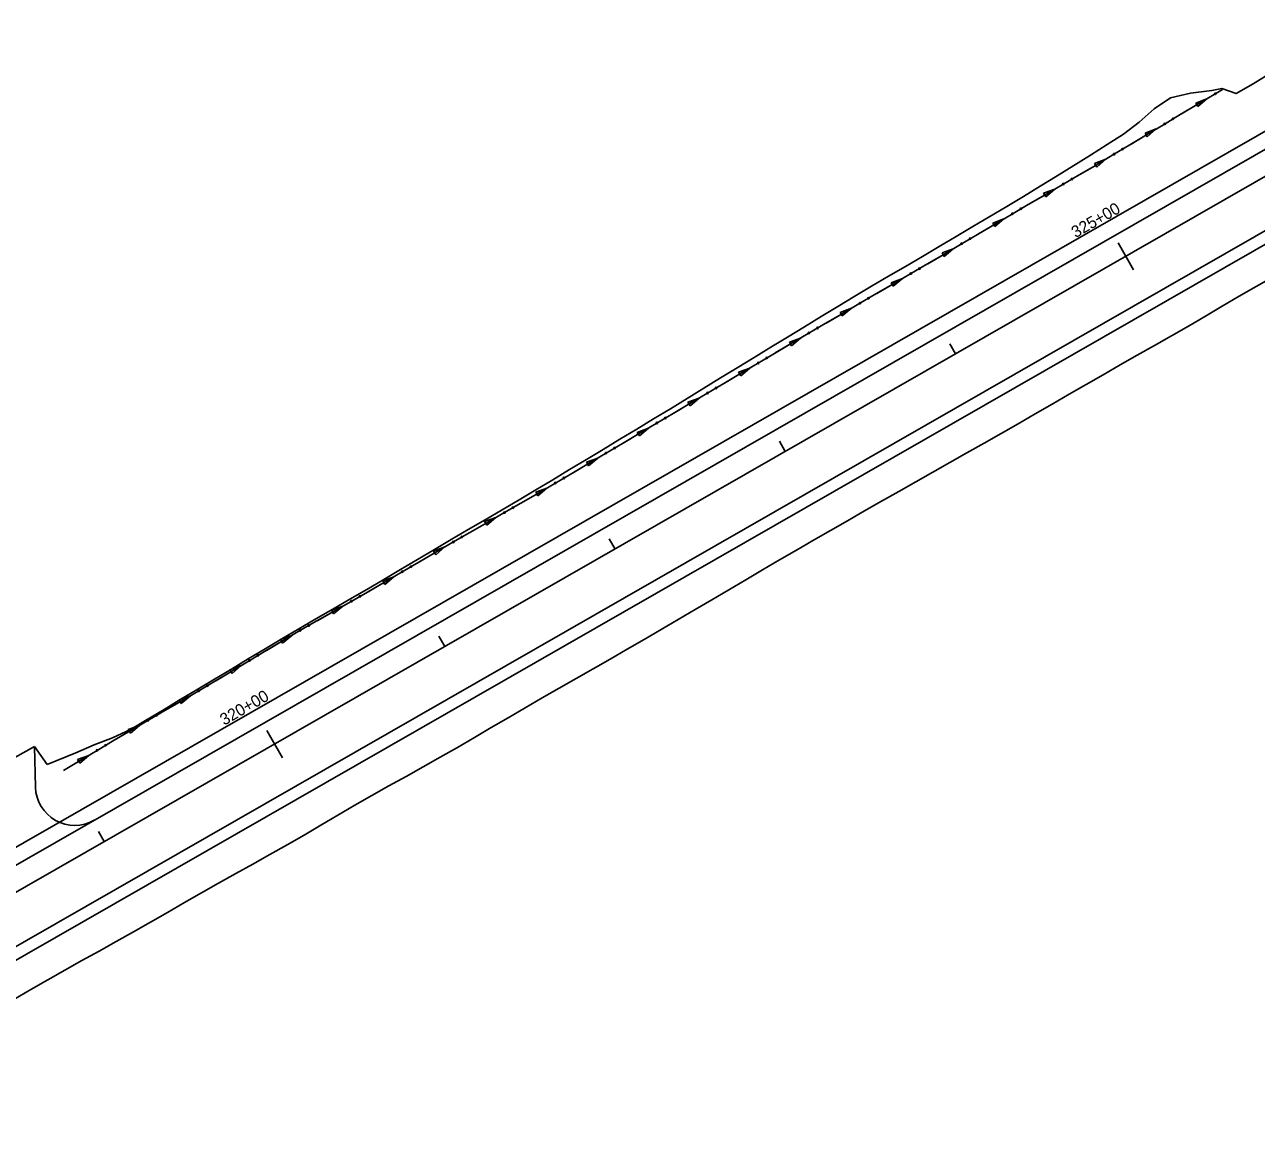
# Model space of a CAD drawing. Extents: x 1375694 to 1433473, y 1931050 to 1967991.
# Drawn here: x 1418280 to 1418908, y 1956117 to 1956684 of the extents above; entities that cross this region are included whole.
import ezdxf

# ---------------------------------------------------------------- set-up
doc = ezdxf.new("R2010")
doc.units = 0
for name, color, linetype in [('62', 7, 'Continuous'), ('R_Horz Alg', 7, 'Continuous'), ('R_Horz Alg Annot', 7, 'Continuous'), ('R_Proposed Const Limits', 7, 'Continuous'), ('R_Proposed Road', 7, 'Continuous')]:
    doc.layers.add(name, color=color, linetype=linetype)

msp = doc.modelspace()

# ---------------------------------------------------------------- linework, layer by layer
at = {"layer": '62'}
for p, q in [((1418882.71, 1956645.8), (1418877.01, 1956643.66)), ((1418877.01, 1956643.66), (1418878.08, 1956641.84)), ((1418878.08, 1956641.84), (1418882.71, 1956645.8)), ((1418856.9, 1956630.44), (1418851.21, 1956628.26)), ((1418852.29, 1956626.45), (1418856.9, 1956630.44)), ((1418851.21, 1956628.26), (1418852.29, 1956626.45)), ((1418831.13, 1956615), (1418825.44, 1956612.82)), ((1418825.44, 1956612.82), (1418826.53, 1956611.01)), ((1418826.53, 1956611.01), (1418831.13, 1956615)), ((1418805.22, 1956599.81), (1418799.5, 1956597.7)), ((1418800.57, 1956595.87), (1418805.22, 1956599.81)), ((1418799.5, 1956597.7), (1418800.57, 1956595.87)), ((1418779.29, 1956584.64), (1418773.59, 1956582.5)), ((1418773.59, 1956582.5), (1418774.66, 1956580.68)), ((1418774.66, 1956580.68), (1418779.29, 1956584.64)), ((1418753.42, 1956569.37), (1418747.72, 1956567.23)), ((1418747.72, 1956567.23), (1418748.79, 1956565.41)), ((1418748.79, 1956565.41), (1418753.42, 1956569.37)), ((1418727.51, 1956554.18), (1418721.79, 1956552.07)), ((1418721.79, 1956552.07), (1418722.86, 1956550.25)), ((1418722.86, 1956550.25), (1418727.51, 1956554.18)), ((1418701.55, 1956539.06), (1418695.84, 1956536.95)), ((1418695.84, 1956536.95), (1418696.9, 1956535.12)), ((1418696.9, 1956535.12), (1418701.55, 1956539.06)), ((1418675.65, 1956523.85), (1418669.95, 1956521.72)), ((1418671.02, 1956519.89), (1418675.65, 1956523.85)), ((1418669.95, 1956521.72), (1418671.02, 1956519.89)), ((1418649.78, 1956508.58), (1418644.08, 1956506.44)), ((1418644.08, 1956506.44), (1418645.16, 1956504.62)), ((1418645.16, 1956504.62), (1418649.78, 1956508.58)), ((1418623.94, 1956493.27), (1418618.24, 1956491.12)), ((1418619.32, 1956489.3), (1418623.94, 1956493.27)), ((1418618.24, 1956491.12), (1418619.32, 1956489.3)), ((1418598.11, 1956477.94), (1418592.41, 1956475.79)), ((1418592.41, 1956475.79), (1418593.49, 1956473.97)), ((1418593.49, 1956473.97), (1418598.11, 1956477.94)), ((1418572.26, 1956462.64), (1418566.55, 1956460.51)), ((1418566.55, 1956460.51), (1418567.63, 1956458.68)), ((1418567.63, 1956458.68), (1418572.26, 1956462.64)), ((1418546.38, 1956447.4), (1418540.67, 1956445.26)), ((1418540.67, 1956445.26), (1418541.75, 1956443.44)), ((1418541.75, 1956443.44), (1418546.38, 1956447.4)), ((1418520.37, 1956432.37), (1418514.64, 1956430.3)), ((1418514.64, 1956430.3), (1418515.69, 1956428.46)), ((1418515.69, 1956428.46), (1418520.37, 1956432.37)), ((1418494.35, 1956417.36), (1418488.64, 1956415.24)), ((1418489.7, 1956413.42), (1418494.35, 1956417.36)), ((1418488.64, 1956415.24), (1418489.7, 1956413.42)), ((1418468.42, 1956402.2), (1418462.7, 1956400.09)), ((1418462.7, 1956400.09), (1418463.77, 1956398.26)), ((1418463.77, 1956398.26), (1418468.42, 1956402.2)), ((1418442.39, 1956387.21), (1418436.65, 1956385.15)), ((1418436.65, 1956385.15), (1418437.7, 1956383.32)), ((1418437.7, 1956383.32), (1418442.39, 1956387.21)), ((1418416.33, 1956372.28), (1418410.61, 1956370.16)), ((1418410.61, 1956370.16), (1418411.68, 1956368.33)), ((1418411.68, 1956368.33), (1418416.33, 1956372.28)), ((1418390.53, 1956356.89), (1418384.83, 1956354.72)), ((1418384.83, 1956354.72), (1418385.92, 1956352.91)), ((1418385.92, 1956352.91), (1418390.53, 1956356.89)), ((1418364.7, 1956341.56), (1418358.98, 1956339.45)), ((1418360.05, 1956337.63), (1418364.7, 1956341.56)), ((1418358.98, 1956339.45), (1418360.05, 1956337.63)), ((1418338.75, 1956326.43), (1418333.03, 1956324.32)), ((1418333.03, 1956324.32), (1418334.1, 1956322.49)), ((1418334.1, 1956322.49), (1418338.75, 1956326.43)), ((1418312.89, 1956311.14), (1418307.2, 1956308.98)), ((1418308.28, 1956307.16), (1418312.89, 1956311.14)), ((1418307.2, 1956308.98), (1418308.28, 1956307.16))]:
    msp.add_line(p, q, dxfattribs=at)
for points in [[(1418300.01, 1956303.46), (1418308.6, 1956308.58), (1418317.19, 1956313.69), (1418325.79, 1956318.81), (1418334.4, 1956323.89), (1418343.04, 1956328.93), (1418351.68, 1956333.97), (1418360.32, 1956339.01), (1418368.95, 1956344.05), (1418377.56, 1956349.14), (1418386.14, 1956354.27), (1418394.73, 1956359.41), (1418403.31, 1956364.54), (1418411.89, 1956369.68), (1418420.52, 1956374.73), (1418429.21, 1956379.69), (1418437.89, 1956384.64), (1418446.58, 1956389.6), (1418455.27, 1956394.56), (1418463.92, 1956399.57), (1418472.55, 1956404.62), (1418481.18, 1956409.66), (1418489.82, 1956414.71), (1418498.45, 1956419.76), (1418507.11, 1956424.75), (1418515.79, 1956429.73), (1418524.46, 1956434.72), (1418533.13, 1956439.7), (1418541.79, 1956444.69), (1418550.41, 1956449.77), (1418559.02, 1956454.84), (1418567.64, 1956459.92), (1418576.26, 1956465), (1418584.87, 1956470.08), (1418593.47, 1956475.19), (1418602.07, 1956480.29), (1418610.67, 1956485.4), (1418619.27, 1956490.5), (1418627.87, 1956495.6), (1418636.47, 1956500.7), (1418645.08, 1956505.8), (1418653.68, 1956510.9), (1418662.29, 1956515.99), (1418670.91, 1956521.06), (1418679.53, 1956526.13), (1418688.15, 1956531.2), (1418696.77, 1956536.27), (1418705.41, 1956541.31), (1418714.05, 1956546.34), (1418722.69, 1956551.37), (1418731.34, 1956556.41), (1418739.98, 1956561.44), (1418748.59, 1956566.52), (1418757.2, 1956571.6), (1418765.82, 1956576.69), (1418774.43, 1956581.77), (1418783.04, 1956586.85), (1418791.67, 1956591.91), (1418800.31, 1956596.94), (1418808.95, 1956601.98), (1418817.59, 1956607.01), (1418826.23, 1956612.06), (1418834.8, 1956617.2), (1418843.38, 1956622.34), (1418851.96, 1956627.48), (1418860.54, 1956632.62), (1418869.12, 1956637.77), (1418877.73, 1956642.86), (1418886.34, 1956647.94), (1418890.65, 1956650.48)], [(1418869.8, 1956638.17), (1418877.73, 1956642.86), (1418882.71, 1956645.8)], [(1418869.76, 1956638.15), (1418869.8, 1956638.17)], [(1418844.03, 1956622.73), (1418851.96, 1956627.48), (1418856.9, 1956630.44)], [(1418844, 1956622.71), (1418844.03, 1956622.73)], [(1418818.21, 1956607.38), (1418826.23, 1956612.06), (1418831.13, 1956615)], [(1418818.18, 1956607.36), (1418818.21, 1956607.37)], [(1418792.26, 1956592.26), (1418800.31, 1956596.94), (1418805.22, 1956599.81)], [(1418792.22, 1956592.24), (1418792.26, 1956592.26)], [(1418766.37, 1956577.01), (1418774.43, 1956581.77), (1418779.29, 1956584.64)], [(1418766.34, 1956576.99), (1418766.37, 1956577.01)], [(1418740.5, 1956561.75), (1418748.59, 1956566.52), (1418753.42, 1956569.37)], [(1418740.47, 1956561.73), (1418740.5, 1956561.75)], [(1418714.55, 1956546.63), (1418722.69, 1956551.37), (1418727.51, 1956554.18)], [(1418714.51, 1956546.61), (1418714.55, 1956546.63)], [(1418688.61, 1956531.47), (1418696.77, 1956536.27), (1418701.55, 1956539.06)], [(1418688.58, 1956531.45), (1418688.61, 1956531.47)], [(1418662.73, 1956516.24), (1418670.91, 1956521.06), (1418675.65, 1956523.85)], [(1418662.69, 1956516.22), (1418662.72, 1956516.24)], [(1418636.88, 1956500.94), (1418645.08, 1956505.8), (1418649.78, 1956508.58)], [(1418636.84, 1956500.92), (1418636.88, 1956500.94)], [(1418611.04, 1956485.62), (1418619.27, 1956490.5), (1418623.94, 1956493.27)], [(1418611.01, 1956485.6), (1418611.04, 1956485.62)], [(1418585.21, 1956470.28), (1418593.47, 1956475.19), (1418598.11, 1956477.94)], [(1418585.18, 1956470.26), (1418585.21, 1956470.28)], [(1418559.34, 1956455.03), (1418567.64, 1956459.92), (1418572.26, 1956462.64)], [(1418559.3, 1956455.01), (1418559.34, 1956455.03)], [(1418533.41, 1956439.86), (1418541.79, 1956444.69), (1418546.38, 1956447.4)], [(1418533.38, 1956439.84), (1418533.41, 1956439.86)], [(1418507.36, 1956424.9), (1418515.79, 1956429.73), (1418520.37, 1956432.37)], [(1418507.33, 1956424.88), (1418507.36, 1956424.89)], [(1418481.4, 1956409.79), (1418489.82, 1956414.71), (1418494.35, 1956417.36)], [(1418481.37, 1956409.77), (1418481.4, 1956409.79)], [(1418455.45, 1956394.66), (1418463.92, 1956399.57), (1418468.42, 1956402.2)], [(1418455.42, 1956394.64), (1418455.45, 1956394.66)], [(1418429.36, 1956379.78), (1418437.89, 1956384.64), (1418442.39, 1956387.21)], [(1418429.33, 1956379.76), (1418429.36, 1956379.78)], [(1418403.43, 1956364.62), (1418411.89, 1956369.68), (1418416.33, 1956372.28)], [(1418403.4, 1956364.6), (1418403.43, 1956364.62)], [(1418377.65, 1956349.19), (1418386.14, 1956354.27), (1418390.53, 1956356.89)], [(1418377.62, 1956349.17), (1418377.65, 1956349.19)], [(1418351.74, 1956334), (1418360.32, 1956339.01), (1418364.7, 1956341.56)], [(1418351.71, 1956333.99), (1418351.74, 1956334)], [(1418325.82, 1956318.83), (1418334.4, 1956323.89), (1418338.75, 1956326.43)], [(1418325.79, 1956318.81), (1418325.79, 1956318.81), (1418325.82, 1956318.82)], [(1418300.01, 1956303.46), (1418308.6, 1956308.58), (1418312.89, 1956311.14)]]:
    msp.add_lwpolyline(points, dxfattribs=at)
for centre in [(1418887.01, 1956648.37), (1418861.17, 1956633.04), (1418865.47, 1956635.62), (1418835.41, 1956617.6), (1418839.7, 1956620.18), (1418813.86, 1956604.88), (1418809.53, 1956602.36), (1418783.59, 1956587.21), (1418787.91, 1956589.75), (1418762.03, 1956574.49), (1418757.72, 1956571.95), (1418731.82, 1956556.73), (1418736.15, 1956559.25), (1418710.19, 1956544.14), (1418705.86, 1956541.62), (1418679.95, 1956526.42), (1418684.27, 1956528.96), (1418654.07, 1956511.17), (1418658.38, 1956513.72), (1418632.54, 1956498.41), (1418628.23, 1956495.86), (1418602.4, 1956480.53), (1418606.7, 1956483.09), (1418580.87, 1956467.76), (1418576.55, 1956465.21), (1418550.67, 1956449.97), (1418554.99, 1956452.51), (1418529.04, 1956437.39), (1418524.69, 1956434.89), (1418503, 1956422.42), (1418498.66, 1956419.92), (1418472.72, 1956404.76), (1418477.05, 1956407.29), (1418451.07, 1956392.2), (1418446.72, 1956389.72), (1418420.63, 1956374.84), (1418424.98, 1956377.32), (1418399.1, 1956362.07), (1418394.8, 1956359.5), (1418369, 1956344.11), (1418373.31, 1956346.67), (1418343.05, 1956328.98), (1418347.38, 1956331.51), (1418321.48, 1956316.29), (1418317.18, 1956313.73)]:
    msp.add_circle(centre, 0.375, dxfattribs=at)
at = {"layer": 'R_Horz Alg'}
msp.add_line((1418104.96, 1956143.46), (1420966.37, 1957783.31), dxfattribs=at)
at = {"layer": 'R_Horz Alg Annot'}
for points in [[(1418837.4, 1956572.44), (1418845.36, 1956558.56)], [(1418751.63, 1956520.98), (1418754.62, 1956515.78)], [(1418664.87, 1956471.26), (1418667.86, 1956466.06)], [(1418578.11, 1956421.54), (1418581.09, 1956416.33)], [(1418491.35, 1956371.82), (1418494.33, 1956366.61)], [(1418403.59, 1956323.83), (1418411.55, 1956309.95)], [(1418317.82, 1956272.37), (1418320.81, 1956267.17)]]:
    msp.add_lwpolyline(points, dxfattribs=at)
at = {"layer": 'R_Proposed Const Limits'}
for points in [[(1418890.35, 1956651.01), (1418897.55, 1956648.49), (1418906.25, 1956653.43), (1418914.79, 1956658.64)], [(1418291.74, 1956306.46), (1418306.34, 1956312.51), (1418315.61, 1956316.45), (1418325.05, 1956320.09), (1418334.15, 1956324.32), (1418342.72, 1956329.49), (1418351.32, 1956334.6), (1418359.9, 1956339.73), (1418368.48, 1956344.87), (1418377.05, 1956350.04), (1418385.64, 1956355.16), (1418394.21, 1956360.31), (1418402.81, 1956365.41), (1418411.37, 1956370.6), (1418419.96, 1956375.71), (1418428.61, 1956380.73), (1418437.27, 1956385.73), (1418445.93, 1956390.74), (1418454.58, 1956395.75), (1418463.21, 1956400.81), (1418471.81, 1956405.91), (1418480.42, 1956411), (1418489.02, 1956416.09), (1418497.63, 1956421.19), (1418506.26, 1956426.24), (1418514.91, 1956431.27), (1418523.55, 1956436.3), (1418532.17, 1956441.37), (1418540.78, 1956446.45), (1418549.35, 1956451.61), (1418557.92, 1956456.77), (1418566.49, 1956461.93), (1418575.06, 1956467.09), (1418583.62, 1956472.25), (1418592.18, 1956477.44), (1418600.73, 1956482.63), (1418609.28, 1956487.83), (1418617.8, 1956493.06), (1418626.33, 1956498.29), (1418634.87, 1956503.51), (1418643.4, 1956508.73), (1418651.93, 1956513.96), (1418660.47, 1956519.17), (1418669.01, 1956524.37), (1418677.56, 1956529.57), (1418686.1, 1956534.77), (1418694.65, 1956539.97), (1418703.21, 1956545.14), (1418711.81, 1956550.26), (1418720.43, 1956555.32), (1418729.06, 1956560.38), (1418737.69, 1956565.43), (1418746.28, 1956570.54), (1418754.88, 1956575.65), (1418763.48, 1956580.76), (1418772.08, 1956585.87), (1418780.67, 1956590.98), (1418789.28, 1956596.07), (1418797.81, 1956601.31), (1418806.33, 1956606.55), (1418814.84, 1956611.82), (1418823.36, 1956617.06), (1418831.8, 1956622.44), (1418840.24, 1956627.82), (1418848.25, 1956633.95), (1418855.9, 1956640.72), (1418864.21, 1956646.34), (1418874.4, 1956648.66), (1418885.15, 1956650.02), (1418890.35, 1956651.01)], [(1418274.67, 1956186.77), (1418283.32, 1956191.8), (1418292, 1956196.77), (1418300.71, 1956201.68), (1418309.45, 1956206.54), (1418318.18, 1956211.41), (1418326.93, 1956216.26), (1418335.64, 1956221.17), (1418344.32, 1956226.14), (1418353, 1956231.11), (1418361.66, 1956236.11), (1418370.34, 1956241.07), (1418379.05, 1956245.98), (1418387.79, 1956250.85), (1418396.52, 1956255.72), (1418405.21, 1956260.66), (1418413.96, 1956265.52), (1418422.62, 1956270.52), (1418431.23, 1956275.61), (1418439.89, 1956280.6), (1418448.5, 1956285.69), (1418457.15, 1956290.71), (1418465.84, 1956295.65), (1418474.62, 1956300.45), (1418483.32, 1956305.37), (1418492.03, 1956310.29), (1418500.74, 1956315.21), (1418509.4, 1956320.2), (1418518.02, 1956325.27), (1418526.64, 1956330.34), (1418535.28, 1956335.38), (1418543.91, 1956340.43), (1418552.58, 1956345.42), (1418561.25, 1956350.4), (1418569.95, 1956355.33), (1418578.66, 1956360.25), (1418587.35, 1956365.2), (1418595.98, 1956370.25), (1418604.62, 1956375.28), (1418613.24, 1956380.35), (1418621.87, 1956385.41), (1418630.5, 1956390.46), (1418639.11, 1956395.54), (1418647.71, 1956400.64), (1418656.32, 1956405.74), (1418664.94, 1956410.8), (1418673.61, 1956415.79), (1418682.28, 1956420.78), (1418690.95, 1956425.76), (1418699.61, 1956430.77), (1418708.28, 1956435.75), (1418716.96, 1956440.7), (1418725.65, 1956445.65), (1418734.33, 1956450.62), (1418743.02, 1956455.58), (1418751.73, 1956460.49), (1418760.43, 1956465.42), (1418769.13, 1956470.34), (1418777.84, 1956475.26), (1418786.53, 1956480.2), (1418795.2, 1956485.18), (1418803.86, 1956490.19), (1418812.53, 1956495.18), (1418821.2, 1956500.16), (1418829.85, 1956505.17), (1418838.54, 1956510.13), (1418847.22, 1956515.09), (1418855.93, 1956520), (1418864.61, 1956524.97), (1418873.31, 1956529.9), (1418881.91, 1956535.01), (1418890.55, 1956540.04), (1418899.15, 1956545.14), (1418907.79, 1956550.18), (1418916.48, 1956555.12)], [(1418285.19, 1956315.65), (1418291.74, 1956306.46)]]:
    msp.add_lwpolyline(points, dxfattribs=at)
at = {"layer": 'R_Proposed Road'}
for p, q in [((1418095.01, 1956160.82), (1420956.43, 1957800.66)), ((1418098.99, 1956153.88), (1420960.4, 1957793.72)), ((1418116.89, 1956122.64), (1420978.3, 1957762.49)), ((1418119.87, 1956117.44), (1420981.29, 1957757.28)), ((1418269.43, 1956306.8), (1418285.19, 1956315.65)), ((1418285.19, 1956315.65), (1418285.77, 1956294.87))]:
    msp.add_line(p, q, dxfattribs=at)
msp.add_arc((1418305.76, 1956295.43), 20, 181.58794, 299.81658, dxfattribs=at)

# ---------------------------------------------------------------- texts
at = {"layer": 'R_Horz Alg Annot'}
for s, p in [('325+00', (1418815.77, 1956574.71)), ('320+00', (1418381.9, 1956326.21))]:
    msp.add_text(s, height=6, rotation=29.81658, dxfattribs=at).set_placement(p)

doc.saveas('drawing.dxf')
